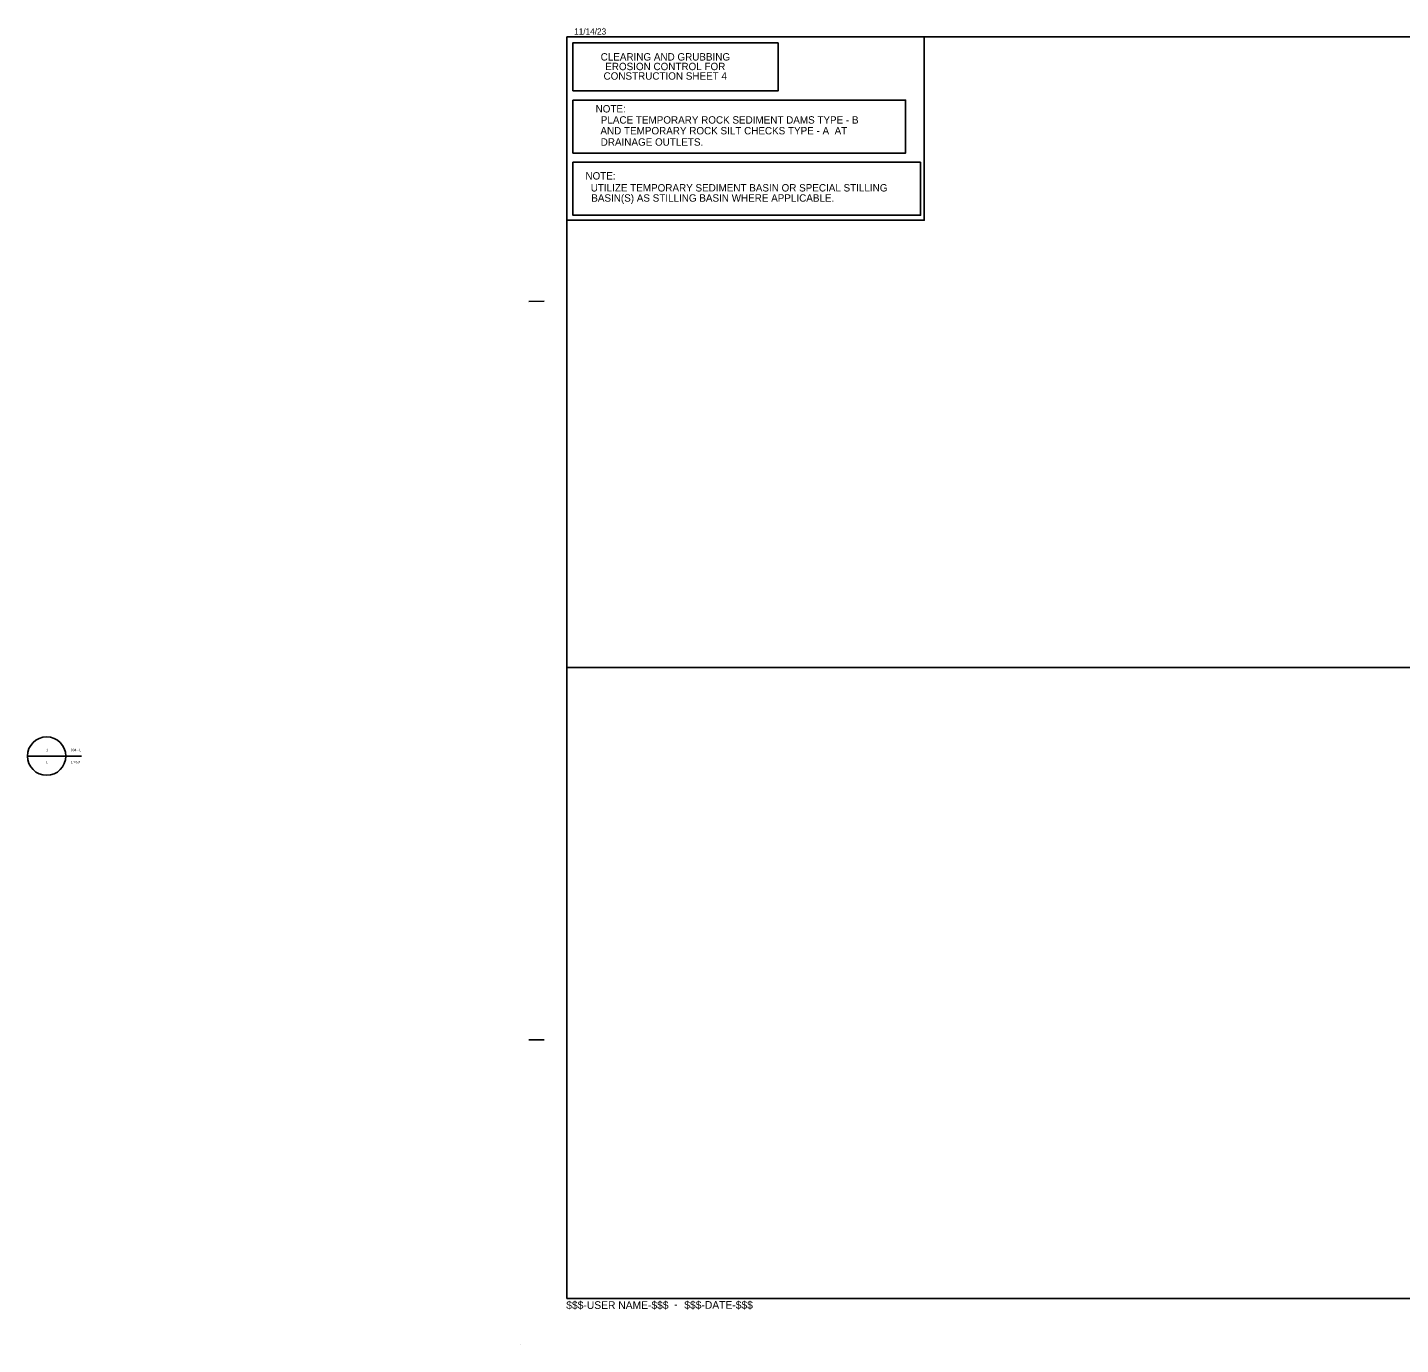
# Model space of a CAD drawing. Extents: x -0.67 to 3.05, y 0 to 1.8.
# Drawn here: x -0.668 to 1.192, y 0 to 1.783 of the extents above; entities that cross this region are included whole.
import ezdxf

# ---------------------------------------------------------------- set-up
doc = ezdxf.new("R2010")
doc.units = 0
for name, color, linetype in [('Construction Sheet Number Note CG CELL', 7, 'Continuous'), ('Default', 7, 'Continuous'), ('Exist Environmental Wetland Boundary Cogo Number', 7, 'Continuous'), ('Exist Hydro Stream or Body of Water Cogo Point CELL', 7, 'Continuous'), ('Exist Hydro Swamp or Marsh', 7, 'Continuous'), ('Scratch_Level_0', 7, 'Continuous'), ('Sediment Dams and Silt Check Note CG CELL', 7, 'Continuous'), ('Use Temporary Sed Dam as Stilling Basin Note Both CELL', 7, 'Continuous')]:
    doc.layers.add(name, color=color, linetype=linetype)

msp = doc.modelspace()

# ---------------------------------------------------------------- linework, layer by layer
at = {"layer": 'Construction Sheet Number Note CG CELL'}
msp.add_lwpolyline([(0.3487, 1.7628), (0.0705, 1.7628), (0.0705, 1.6978), (0.3487, 1.6978)], close=True, dxfattribs=at)
at = {"layer": 'Default'}
for p, q in [((-0.6684, 0.7968), (-0.6163, 0.7968)), ((-0.6421, 0.7968), (-0.5954, 0.7968))]:
    msp.add_line(p, q, dxfattribs=at)
msp.add_circle((-0.6424, 0.7968), 0.026, dxfattribs=at)
at = {"layer": 'Exist Environmental Wetland Boundary Cogo Number'}
msp.add_line((0, 0), (0, 0), dxfattribs=at)
at = {"layer": 'Exist Hydro Stream or Body of Water Cogo Point CELL'}
msp.add_line((0.0625, 0.9167), (2.6041, 0.9167), dxfattribs=at)
msp.add_lwpolyline([(0.0625, 0.0625), (2.6041, 0.0625), (2.6042, 1.7708), (0.5467, 1.7708), (0.5467, 1.5224), (0.0625, 1.5224)], close=True, dxfattribs=at)
at = {"layer": 'Exist Hydro Swamp or Marsh'}
for p, q in [((0.0625, 0.0625), (0.0625, 1.7708)), ((2.7708, 1.7708), (0.0625, 1.7708)), ((0.1124, 1.7834), (0.1124, 1.7834)), ((0.0108, 1.4125), (0.0317, 1.4126)), ((0.0109, 0.4125), (0.0317, 0.4125)), ((0.0625, 0.0625), (2.7708, 0.0625))]:
    msp.add_line(p, q, dxfattribs=at)
at = {"layer": 'Scratch_Level_0'}
msp.add_lwpolyline([(0.0625, 1.7708), (0.5467, 1.7708), (0.5467, 1.5224), (0.0625, 1.5224)], close=True, dxfattribs=at)
at = {"layer": 'Sediment Dams and Silt Check Note CG CELL'}
msp.add_lwpolyline([(0.0705, 1.685), (0.0705, 1.6132), (0.5212, 1.6132), (0.5212, 1.685)], close=True, dxfattribs=at)
at = {"layer": 'Use Temporary Sed Dam as Stilling Basin Note Both CELL'}
msp.add_lwpolyline([(0.5417, 1.6008), (0.0705, 1.6008), (0.0705, 1.5291), (0.5417, 1.5291)], close=True, dxfattribs=at)

# ---------------------------------------------------------------- texts
at = {"layer": 'Construction Sheet Number Note CG CELL'}
for s, p in [('CLEARING AND GRUBBING', (0.1082, 1.7386)), ('EROSION CONTROL FOR', (0.1144, 1.7256)), ('CONSTRUCTION SHEET 4', (0.1121, 1.7127))]:
    msp.add_text(s, height=0.01, dxfattribs=at).set_placement(p)
at = {"layer": 'Default'}
for s, p in [('1', (-0.6432, 0.8034)), ('004 - L', (-0.6096, 0.8034)), ('L', (-0.6433, 0.787)), ('1"=50\'', (-0.6096, 0.787))]:
    msp.add_text(s, height=0.00328, dxfattribs=at).set_placement(p)
at = {"layer": 'Exist Hydro Swamp or Marsh'}
msp.add_text('11/14/23', height=0.00833, rotation=0, dxfattribs=at).set_placement((0.0723, 1.7738))
for s, height, p in [('$$$-USER NAME-$$$', 0.010417, (0.0616, 0.0482)), ('$$$-DATE-$$$', 0.010417, (0.2215, 0.0484)), ('-', 0.0104, (0.2078, 0.0492))]:
    msp.add_text(s, height=height, dxfattribs=at).set_placement(p)
at = {"layer": 'Sediment Dams and Silt Check Note CG CELL'}
for s, p in [('NOTE:', (0.1013, 1.6683)), ('     PLACE TEMPORARY ROCK SEDIMENT DAMS TYPE - B', (0.0898, 1.6532)), ('     AND TEMPORARY ROCK SILT CHECKS TYPE - A  AT', (0.0893, 1.6386)), ('     DRAINAGE OUTLETS.', (0.0897, 1.6233))]:
    msp.add_text(s, height=0.01, dxfattribs=at).set_placement(p)
at = {"layer": 'Use Temporary Sed Dam as Stilling Basin Note Both CELL'}
for s, p in [('NOTE:  ', (0.0876, 1.5775)), ('     UTILIZE TEMPORARY SEDIMENT BASIN OR SPECIAL STILLING', (0.0762, 1.5613)), ('     BASIN(S) AS STILLING BASIN WHERE APPLICABLE.', (0.0769, 1.5475))]:
    msp.add_text(s, height=0.01, dxfattribs=at).set_placement(p)

doc.saveas('drawing.dxf')
